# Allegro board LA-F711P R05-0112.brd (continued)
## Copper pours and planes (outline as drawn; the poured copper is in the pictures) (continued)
+PWR_SRC on TOP (solid shape): 130.69,128.12 131.24,128.12 131.24,128.66 131.49,128.66 131.49,128.12 132.95,128.12 133.78,127.28 133.78,124.36 135.17,122.96 135.17,117.62 133.97,116.42 130.15,116.42 129.77,116.04 129.77,115.28 131.11,113.94 136.32,113.94 136.7,113.56 136.7,112.42 136.44,112.17 135.47,112.17 135.45,112.14 129.38,112.14 128,110.77 127.17,110.77 127.04,110.9 127.04,111.28 127.11,111.34 127.89,111.34 128.49,111.94 128.49,113.97 127.43,115.03 125.3,115.03 124.84,115.48 124.84,116.73 125.75,117.63 125.75,122.21 128.93,125.39 128.93,127.92 129.13,128.12 130.44,128.12 130.44,128.66 130.69,128.66
+PWR_SRC on BOTTOM (solid shape): 136.44,114.07 136.44,112.55 136.19,112.29 133.9,112.29 133.52,112.67 133.52,114.07 133.78,114.32 136.19,114.32
+PWR_SRC on BOTTOM (solid shape): 37.73,59.94 40.8,59.94 41.85,58.9 41.85,54.43 40.92,53.49 35.61,53.49 35.39,53.71 35.39,54.99 35.63,55.22 36.17,55.22 36.29,55.35 36.29,59.41 36.3,59.41 36.3,60.32 36.41,60.43 37.25,60.43
+PWR_SRC on BOTTOM (solid shape): 79.65,6.22 80.69,6.22 80.77,6.14 80.77,5.65 81.32,5.65 81.32,5.39 80.77,5.39 80.77,4.85 81.32,4.85 81.32,4.59 80.77,4.59 80.77,3.69 80.32,3.24 78.22,3.24 78.08,3.38 78.08,6.46 78.24,6.63 79.24,6.63
+PWR_SRC on BOTTOM (solid shape): outline of 270 points within 20.47,1.42 168.28,41.53
+PWR_SRC on TOP: outline of 116 points within 19.44,1.37 80.6,58.44
+PWR_SRC on TOP: 161.15,6.64 162.44,6.64 163,6.08 163.35,6.08 163.35,6.08 163.71,6.08 164.38,5.4 164.38,3.14 164.3,3.05 163.6,3.05 163.23,3.42 163.23,4.19 161.67,5.75 161.1,5.75 160.98,5.87 160.98,6.48
+PWR_SRC on BOTTOM: 160.99,6.55 162.16,6.55 162.77,5.94 164.13,5.94 164.25,5.83 164.25,3.73 164.08,3.57 163.01,3.57 160.9,5.68 160.9,6.46
+PWR_SRC on IN1: 156.88,3.19 155.94,4.13 155.94,6.74 156.35,7.15 162.05,7.15 162.44,6.76 162.44,6.18 163.06,5.56 163.06,5.03 162.94,4.9 161.73,4.9 161.43,5.21 160.68,5.21 160.45,5.22 160.22,5.21 159.41,5.21 157.39,3.19
+PWR_SRC on IN1: 81.64,1.31 81.58,1.37 40.38,1.37 40.38,1.37 34.91,1.37 32.78,3.5 29.84,3.5 20.65,12.7 20.65,16.26 20.24,16.66 20.24,20.52 21.43,21.72 21.42,21.72 21.42,22.73 22.13,23.44 22.13,26.3 24.93,29.1 24.93,39.85 23.54,41.24 23.54,51.23 30.88,58.57 39.86,58.57 40.09,58.34 40.09,54.11 39.85,53.87 34.46,53.87 30.02,49.43 30.02,45.73 29.99,45.65 29.91,45.62 28.97,44.74 29.91,43.85 29.99,43.82 30.02,43.75 30.02,42.21 29.75,42.48 29.43,42.48 29.21,42.26 29.21,39.9 30.02,39.08 30.02,37.24 31.29,35.97 31.29,27.58 26.44,22.73 26.44,18.93 26.14,18.2 26.44,17.46 26.44,16.33 26.44,16.28 26.44,16.24 26.44,14.99 26.45,14.97 26.45,14.13 29.43,11.15 35.07,11.15 36.18,10.05 36.18,6.21 36.72,5.66 41.3,5.66 41.41,5.55 41.47,5.55 41.88,5.13 41.88,5.1 42.59,4.4 42.59,3.43 42.97,3.05 77.26,3.05 78.47,4.26 78.47,5.73 78.99,6.26 80.35,6.26 80.36,6.24 80.79,6.24 80.93,6.1 80.93,3.7 82.31,2.33 86.33,2.33 86.46,2.2 86.46,1.31
+PWR_SRC on VCC: 18.72,1.17 18.72,35.16 22.91,39.35 22.91,57.37 36.92,57.37 37.36,57.81 39.99,57.81 39.99,45.15 23.61,28.77 23.61,13.32 26.23,10.69 35.44,10.69 36.05,10.08 36.05,6.59 38.3,4.34 42.61,4.34 43.63,3.33 76.1,3.33 78.89,6.12 80.33,6.12 81.2,5.25 81.2,1.17
+PWR_SRC_AC on TOP (solid shape): 22.53,53.52 22.53,45.11 22.14,44.73 17.57,44.73 17.19,45.11 17.19,47.6 13.52,51.27 13.52,54.3 13.42,54.41 12.76,54.41 12.56,54.61 12.56,55.13 12.58,55.16 13.33,55.16 13.48,55.3 13.48,55.75 13.31,55.92 12.63,55.92 12.56,55.99 12.56,57.03 12.78,57.25 18.79,57.25
+PWR_SRC_AC on BOTTOM (solid shape): 22.53,47.95 22.53,47.34 22.53,47.33 22.53,45.31 22.05,44.83 20.45,44.83 20.45,44.32 19.96,44.32 19.96,44.83 19.25,44.83 19.25,44.32 18.76,44.32 18.76,44.83 17.98,44.83 17.1,45.72 17.1,47.38 18.2,48.49 21.99,48.49
+REGCTL_PNP10 on TOP (solid shape): 327.19,87.15 327.19,85.88 327.06,85.76 325.99,85.76 325.54,86.2 325.03,86.2 324.84,86.39 323.82,86.39 323.76,86.45 323.76,86.58 323.81,86.63 325.78,86.63 326.43,87.28 327.06,87.28
+RREF on TOP (solid shape): 16.55,66.26 16.55,65.5 16.17,65.12 14.83,65.12 14.07,64.36 14.07,63.47 14.01,63.4 13.5,63.4 13.44,63.47 13.44,64.42 14.71,65.69 15.72,65.69 16.36,66.32 16.49,66.32
+RSVD_VCC3P3_1 on TOP (solid shape): 325.09,83.85 325.09,83.22 324.9,83.03 324.65,83.03 323.76,83.91 323.76,84.17 323.82,84.23 324.71,84.23
+RTC_CELL_PCH on TOP: 213.2,16.75 213.2,15.8 213.8,15.2 213.8,12.22 214.16,11.86 216.02,11.86 216.42,12.25 216.42,14.46 217.18,15.23 217.18,16.73 217.09,16.81 213.27,16.81
+SDC_IN on TOP (solid shape): 11.55,60.86 11.55,56.02 11.46,55.93 10.83,55.93 10.62,55.72 10.62,55.29 10.75,55.17 11.5,55.17 11.54,55.13 11.54,54.63 11.31,54.41 3.27,54.41 2.36,55.32 2.36,64.45 2.98,65.07 7.34,65.07
+SDC_IN on TOP (solid shape): outline of 140 points within 39.63,87.88 61.13,119.53
+SDC_IN on IN1 (solid shape): 8.58,68.4 8.58,59.64 7.39,58.44 3.6,58.44 3.48,58.57 3.48,68.26 3.74,68.53 8.45,68.53
+SDC_IN on IN1 (solid shape): 43.89,97.19 43.89,91.27 43.9,91.27 44.03,91.15 44.03,88.91 43.73,88.62 41.41,88.62 40.79,89.24 40.79,97.05 41.17,97.43 43.65,97.43
+TBTA_VBUS on TOP (solid shape): 7.78,112.48 10.4,112.48 10.71,112.17 11.1,112.17 11.35,111.91 11.35,111.28 11.12,111.05 8.51,111.05 7.97,111.58 6.9,111.58 6.7,111.78 6.7,112.39 6.78,112.47 7.21,112.47 7.39,112.65 7.61,112.65
+TBTA_VBUS on TOP (solid shape): outline of 201 points within 6.72,114.61 13.89,124.23
+TBTA_VBUS on BOTTOM (solid shape): 17.83,124.99 17.83,119.73 17.78,119.68 11.3,119.68 10.15,120.83 10.15,121.26 10.42,122.24 10.44,123.25 10.41,123.43 10.38,123.6 10.4,123.69 10.48,123.72 10.91,124.16 11.3,124.16 11.32,124.13 12.84,124.13 13.38,123.6 14.14,123.6 14.65,124.1 14.65,124.87 15.03,125.25 17.57,125.25
+TBTA_VBUS on BOTTOM (solid shape): 10.68,112.19 11.13,112.19 11.22,112.1 11.22,111.72 10.91,111.4 9.87,111.4 9.17,112.11 8.97,112.11 8.71,112.36 8.13,112.36 8.07,112.39 8,112.39 7.39,112.39 7.21,112.32 7.13,112.14 6.95,111.96 6.85,111.96 6.59,112.23 6.03,112.23 5.97,112.29 5.97,112.47 6,112.51 6.7,112.51 6.97,112.45 7.2,112.6 7.45,112.85 10.02,112.85
+TBTA_VBUS on BOTTOM (solid shape): 10.66,115.52 10.66,114.7 10.44,114.47 9.04,114.47 8.65,114.86 8.13,114.86 8.07,114.89 8,114.89 7.39,114.89 7.31,114.88 7.23,114.84 7.15,114.87 6.89,114.91 6.73,114.85 6.59,114.85 6.5,114.76 5.86,114.76 5.86,114.99 6.32,114.99 6.46,115.13 6.5,115.13 6.66,115.19 6.74,115.34 6.75,115.35 6.93,115.35 6.94,115.37 7.5,115.37 7.52,115.38 7.55,115.38 8.15,115.38 8.17,115.37 8.72,115.37 9.04,115.68 9.15,115.68 9.17,115.7 10.49,115.7
+TBTA_VBUS on IN1 (solid shape): outline of 350 points within 6.72,111.48 13.89,124.23
+TBTA_VBUS on IN2 (solid shape): outline of 281 points within 6.6,111.4 14.17,124.51
+TBTA_VBUS_1 on TOP (solid shape): 24.06,124.9 24.06,123.6 24.61,123.6 24.61,123.15 24.06,123.15 24.06,122.4 24.61,122.4 24.61,121.95 24.06,121.95 24.06,120.56 23.92,120.42 19.22,120.42 18.59,121.06 18.59,124.48 19.1,124.99 23.97,124.99
+TBTA_VBUS_1 on TOP (solid shape): outline of 407 points within 30.62,85.01 39.7,114.07
+TBTA_VBUS_1 on BOTTOM (solid shape): 24.43,124.43 24.43,120.55 24.25,120.37 19.94,120.37 19.5,120.8 18.87,120.8 18.59,121.08 18.59,124 18.77,124.18 21.79,124.18 22.22,124.61 24.25,124.61
+TBTA_VBUS_1 on BOTTOM (solid shape): 34.06,112.93 34.06,112.08 33.74,111.76 32.66,111.76 32.09,111.19 32.09,110.86 32.08,110.85 32.08,109.75 31.9,109.58 31.06,109.58 30.65,109.98 30.65,113.64 31.09,114.07 32.91,114.07
+TBTA_VBUS_1 on BOTTOM (solid shape): 38.68,92.23 38.68,91.34 38.55,91.21 37.51,91.21 37.48,91.18 37.37,91.18 37.37,91.08 37.11,90.82 37.11,90.07 36.12,89.08 35.57,89.08 35.55,89.1 35.28,89.1 35.26,89.1 35.24,89.11 35.17,89.18 35.17,89.38 35.05,89.5 34.83,89.5 34.71,89.63 34.71,89.89 34.73,89.96 34.79,89.99 34.95,89.99 35.08,90.09 35.1,90.09 35.25,90.25 35.25,90.3 35.43,90.48 35.45,90.48 35.54,90.54 35.59,90.63 35.59,90.64 35.68,90.72 35.68,90.92 36.45,91.69 36.86,91.69 37.13,91.97 37.13,92.03 37.5,92.4 38.5,92.4
+TBTA_VBUS_1 on IN1 (solid shape): 27.5,122.07 27.97,122.07 28.01,122.07 28.7,122.07 28.74,122.07 29.24,122.07 29.27,122.06 29.32,122.04 29.38,122.02 29.43,122.02 29.49,122.02 29.55,122.04 29.6,122.06 29.63,122.07 32.31,122.07 34.08,120.3 34.08,117.73 36.14,115.67 36.14,112.39 35.74,111.99 33.02,111.99 32.03,112.99 32.03,115.82 31.47,116.38 31.47,116.43 29.79,118.11 24.35,118.11 22.53,119.94 20.8,119.94 20.11,120.63 27.15,120.63 27.15,120.57 27.16,120.52 27.17,120.47 27.2,120.42 27.23,120.38 27.26,120.34 27.3,120.3 27.35,120.28 27.4,120.26 27.45,120.25 27.5,120.24 27.56,120.25 27.61,120.26 27.66,120.28 27.71,120.3 27.75,120.34 27.78,120.38 27.81,120.42 27.84,120.47 27.85,120.52 27.86,120.57 27.86,120.63 27.85,120.68 27.84,120.73 27.81,120.78 27.78,120.82 27.75,120.86 27.71,120.89 27.66,120.92 27.61,120.94 27.56,120.95 27.5,120.96 27.45,120.95 27.4,120.94 27.35,120.92 27.3,120.89 27.26,120.86 27.23,120.82 27.2,120.78 27.17,120.73 27.16,120.68 27.15,120.63 20.11,120.63 19.48,121.26 19.48,123.32 20.26,124.1 25.47,124.1
+USB_EX2_PWR on BOTTOM (solid shape): 20.9,96.34 20.9,95.45 20.57,95.12 19.1,95.12 18.82,94.84 18.82,93.24 18.77,93.19 18.77,92.43 18.61,92.28 15.87,92.28 15.82,92.33 15.81,92.35 15.6,92.76 15.19,92.97 15.17,92.98 14.45,93.7 14.45,95.76 15.31,96.62 20.62,96.62
+USB_EX3_PWR on TOP (solid shape): 91.26,126.19 91.26,124 91.4,123.86 93.43,123.86 93.72,123.57 93.72,122.55 93.29,122.12 90.5,122.12 90.27,122.35 89.84,122.35 88.74,123.44 88.74,126.42 89.15,126.82 90.62,126.82
+USB_EX3_PWR on BOTTOM (solid shape): 93.54,125.83 93.54,123.29 94.36,122.48 96.31,122.48 96.62,122.17 96.62,121.44 96.57,121.39 96.57,120.24 96.11,119.79 92.73,119.79 92.3,120.22 92.3,120.8 95.19,120.8 95.2,120.75 95.21,120.69 95.23,120.64 95.26,120.59 95.29,120.55 95.33,120.51 95.38,120.48 95.43,120.45 95.48,120.43 95.53,120.42 95.59,120.42 95.65,120.43 95.7,120.44 95.75,120.46 95.8,120.49 95.84,120.53 95.88,120.57 95.91,120.61 95.93,120.67 95.95,120.72 95.96,120.77 95.96,120.83 95.95,120.89 95.93,120.94 95.91,120.99 95.88,121.04 95.84,121.08 95.8,121.11 95.75,121.14 95.7,121.16 95.65,121.18 95.59,121.18 95.53,121.18 95.48,121.17 95.43,121.15 95.38,121.13 95.33,121.1 95.29,121.06 95.26,121.01 95.23,120.96 95.21,120.91 95.2,120.86 95.19,120.8 92.3,120.8 91.03,122.07 91.03,123.16 90.83,123.37 89.96,123.37 89.01,124.32 89.01,126.38 89.48,126.85 92.53,126.85
+UZ12_VHIO on TOP: 242.14,27.62 242.14,29.13 242.29,29.28 242.29,30.28 242.07,30.5 242.07,31.46 242.17,31.55 243.54,31.55 243.73,31.36 243.73,29.86 243.96,29.63 245.01,29.63 245.08,29.56 245.08,29.43 245.03,29.37 244.17,29.37 243.8,29 243.8,27.69 243.68,27.58 242.19,27.58
+VCHGR on TOP (solid shape): 25.19,5.38 25.19,4.93 25.05,4.79 24.43,4.79 24.26,4.62 24.26,4.25 24.49,4.03 25.17,4.03 25.19,4.01 25.19,3.45 25.04,3.3 24.43,3.3 23.97,2.84 23.97,1.49 23.77,1.28 21.04,1.28 20.93,1.4 20.93,5.59 21.08,5.74 24.84,5.74
+VHDMI_VCC on BOTTOM: 115.19,124.51 115.57,124.13 117.09,124.13 117.8,124.84 117.8,125.63 118.54,126.36 120.81,126.36 122.27,124.9 122.27,124.64 122.21,124.57 122.21,124.09 121.87,123.75 121.05,123.75 118.77,121.46 113.46,121.46 112.77,122.15 112.77,128.17 112.57,128.37 112.57,128.56 112.57,128.57 112.63,128.8 112.59,129.03 112.58,129.06 112.82,129.31 114.24,129.31 114.32,129.28 114.35,129.21 114.51,128.91 114.94,128.87 114.98,128.79 114.98,127.86 115.19,127.66 115.19,125.88 115.15,125.81 115.08,125.78 114.69,125.42 115.08,125.07 115.15,125.04 115.19,124.97
+VR_CAP on TOP (solid shape): 313.97,34.07 313.97,33.75 313.91,33.69 313.55,33.69 313.5,33.64 313.39,33.64 312.82,33.07 311.04,33.07 310.82,32.85 310.31,32.85 310.17,32.99 310.17,33.79 310.43,34.06 310.46,34.07 310.49,34.09 310.69,34.09 310.9,33.87 312.5,33.87 312.8,34.17 313.15,34.17 313.16,34.17 313.86,34.17
ADP_ISL88738 on TOP (solid shape): 13.42,36.35 13.42,36.08 13.23,35.89 12.96,35.89 12.71,35.64 12.71,35.38 12.42,35.09 11.53,35.09 11.51,35.11 11.51,35.28 11.55,35.32 12.18,35.32 12.3,35.45 12.3,35.97 12.81,36.47 13.29,36.47
BGATE_ISL88738 on TOP (solid shape): 22.7,6.78 23.41,6.78 23.44,6.76 23.44,6.12 23.24,5.92 21.1,5.92 21.03,5.99 21.03,6.55 21.28,6.81 22.68,6.81
BGATE_ISL88738 on TOP (solid shape): 8.07,32.41 8.07,32.3 8.03,32.26 7.39,32.26 6.61,31.48 6.44,31.48 6.3,31.62 6.3,31.85 6.46,32.01 6.71,32.01 7.17,32.47 8.02,32.47
BOOT1_ISL88738 on BOTTOM (solid shape): 14.29,34.2 14.29,33.38 14.23,33.32 13.61,33.32 13.34,33.59 12.96,33.59 12.8,33.76 12.8,33.76 12.8,34.01 13.03,34.24 14.25,34.24
BOOT2_ISL88738 on TOP: 9.56,32.14 9.66,32.14 9.71,32.09 9.71,31.13 9.43,30.85 9.43,29.95 9.62,29.76 9.88,29.76 9.9,29.73 9.9,29.13 9.81,29.04 9.03,29.04 8.92,29.15 8.92,29.88 9.09,30.05 9.09,30.78 9.51,31.2 9.51,32.09
BST_3V on BOTTOM (solid shape): 89.15,5.89 89.15,4.6 88.93,4.38 88.93,3.49 88.85,3.4 88.24,3.4 88.18,3.45 88.18,4.52 88.74,5.08 88.74,5.99 88.82,6.07 88.97,6.07
BST_5V on TOP (solid shape): 127.15,131.34 127.15,130.4 127.12,130.38 126.26,130.38 125.47,131.17 125.01,131.17 124.91,131.27 124.91,131.42 124.96,131.47 127.02,131.47
BST_+1VALWP on BOTTOM (solid shape): 169.25,5.27 169.25,4.46 169.85,3.86 169.85,3.21 169.82,3.19 168.97,3.19 168.93,3.23 168.93,3.94 169,4 169,5.3 169.05,5.35 169.17,5.35
BST_+1VALWP_R on BOTTOM (solid shape): 171.05,2.46 171.05,1.78 168.96,1.78 168.93,1.8 168.93,2.45 168.98,2.5 171.01,2.5
CNV_RF_RST on BOTTOM (solid shape): 296.31,44.64 296.31,43.85 296.09,43.64 294.86,43.64 294.62,43.88 294.62,44.43 294.76,44.57 295.45,44.57 295.65,44.77 296.18,44.77
CORE_SW1 on BOTTOM (solid shape): 67.89,97.45 67.89,96.16 68.02,96.02 72.53,96.02 73.31,95.24 75.05,95.24 75.57,94.73 77.78,94.73 77.82,94.68 77.82,92.24 77.81,92.23 77.81,92.11 77.76,92.06 76.45,92.06 76.41,92.09 76.41,92.97 76.39,92.98 75.6,92.98 75.59,92.98 75.59,92.07 75.58,92.06 73.8,92.06 73.67,92.19 73.67,92.19 73.56,92.3 73.55,92.3 72.79,93.07 71,93.07 70.71,93.35 70.71,94.12 70.46,94.37 67.52,94.37 67.51,94.38 67.35,94.38 67.12,94.6 67.12,97.46 67.17,97.51 67.83,97.51
CORE_SW1 on TOP: 75.49,92.03 74.53,92.03 74.47,92.09 74.47,92.68 74.25,92.9 73.62,92.9 73.48,93.05 73.48,93.75 73.6,93.87 74.74,93.87 75.59,93.02 75.59,92.13
CORE_SW2 on BOTTOM (solid shape): 77.33,97.62 77.33,96.77 77.45,96.65 77.45,96.31 77.6,96.16 81.43,96.16 81.96,95.63 82.28,95.63 82.28,95.63 83.25,95.63 83.65,95.23 84.99,95.23 85.26,94.95 85.26,93.32 85.26,93.32 85.26,92.11 85.22,92.07 84.01,92.07 83.93,92.16 83.93,92.97 83.91,92.99 83.12,92.99 83.1,92.98 83.1,92.08 83.09,92.07 78.76,92.07 78.13,92.7 78.13,94.71 76.92,95.91 76.92,96.22 76.63,96.51 76.63,97.64 76.64,97.65 77.3,97.65
CORE_SW3 on BOTTOM: 91.35,100.49 90.7,100.49 90.61,100.4 90.61,96.67 90.46,96.52 89.25,96.52 89.12,96.39 89.12,92.42 89.28,92.26 90.62,92.26 90.65,92.28 90.65,93.21 90.66,93.21 91.45,93.21 91.46,93.21 91.46,92.3 91.48,92.28 95.65,92.28 95.88,92.52 95.88,95.39 95.37,95.9 93.68,95.9 93.25,96.34 93.25,97.3 91.58,98.96 91.58,98.96 91.5,99.05 91.5,100.34
CORE_SW4 on BOTTOM (solid shape): 103.26,99.93 103.26,96.38 102.75,95.86 102.75,94.06 102.18,93.49 102.19,93.49 102.19,92.47 102.02,92.3 99,92.3 98.97,92.32 98.97,93.23 98.97,93.23 98.18,93.23 98.17,93.23 98.17,92.3 98.14,92.28 96.53,92.28 96.19,92.62 96.19,93.24 96.77,93.83 96.77,94.67 96.85,94.74 98.64,94.74 98.76,94.86 98.76,96.45 98.8,96.49 99.92,96.49 100.05,96.62 100.05,100.29 100.14,100.39 102.8,100.39
CPU_B+ on BOTTOM (solid shape): 65.4,96.27 65.4,91.85 64.72,91.16 61.98,91.16 61.76,91.39 61.76,94.63 63.64,96.51 65.15,96.51
CPU_B+ on IN3 (solid shape): 88.02,101.78 88.02,99.7 87.72,99.39 86.5,99.39 86.35,99.55 86.35,100.3 85.63,101.01 85.63,101.84 85.87,102.09 87.71,102.09
CPU_B+ on IN3 (solid shape): 97.12,102.89 97.13,102.89 97.53,102.49 97.53,99.69 97.49,99.64 95.9,99.64 94.46,101.08 94.46,102.84 94.66,103.05 96.97,103.05
CPU_B+ on IN3 (solid shape): 73.78,101.02 73.78,98.96 73.44,98.62 73.19,98.62 72.66,98.62 72.66,98.62 71.12,98.62 70.84,98.89 70.84,100.96 71.17,101.29 71.17,101.3 73.51,101.3
CPU_B+ on IN3 (solid shape): 83.06,101.58 83.06,98.94 82.84,98.72 80.81,98.72 80.54,98.99 80.54,100.04 81.09,100.59 81.09,101.54 81.28,101.72 81.28,101.72 81.4,101.83 82.81,101.83
CPU_B+ on TOP: 82.24,98.84 80.76,98.84 80.53,99.07 80.53,100.47 81.16,101.09 81.16,102.78 81.26,102.88 87.53,102.88 87.72,103.07 87.72,104.3 87.87,104.45 88.36,104.45 88.58,104.23 88.58,101.29 88.02,100.72 87.99,100.72 87.99,99.63 87.8,99.43 86.67,99.43 86.54,99.56 86.54,99.77 86.53,99.77 86.53,100.51 86.34,100.7 84.16,100.7 83.68,100.23 83.68,99.85 83.68,99.85 83.68,99.41 83.56,99.29 83.56,99.28 82.67,99.28
CPU_B+ on TOP: 72.31,101.94 72.83,101.94 73.4,102.51 73.4,103.5 73.57,103.68 74.35,103.68 74.6,103.42 74.6,99.71 74.24,99.35 74.24,98.54 74.09,98.39 72.97,98.39 72.72,98.64 71.21,98.64 71.04,98.81 71.04,100.12 72.22,101.29 72.22,101.84
CPU_B+ on TOP: 95.89,104 96.62,104 96.97,103.66 96.97,101.77 97.5,101.24 97.5,99.33 97.36,99.19 96.37,99.19 96.23,99.33 96.23,100.71 96.09,100.85 94.02,100.85 93.9,100.98 93.9,104.83 93.97,104.9 95,104.9
CPU_B+ on BOTTOM: 35.09,60.83 35.25,60.67 40.85,60.67 40.94,60.76 40.94,64.05 39.96,65.02 39.96,65.77 39.38,66.36 35.42,66.36 35.09,66.03
CPU_B+ on BOTTOM: 86.84,98.49 86.77,98.56 86.77,99.88 86.63,100.02 85.83,100.02 85.65,100.2 85.65,104.49 85.87,104.71 85.87,105.65 85.87,105.69 85.6,105.96 83.15,105.96 82.72,105.54 82.72,104.5 82.73,104.5 82.73,103.44 82.72,103.43 82.72,101.55 82.77,101.5 83.58,101.5 83.63,101.45 83.63,99.55 83.49,99.42 82.67,99.42 82.13,98.88 79.52,98.88 79.47,98.93 79.47,99.18 79.47,99.19 79.47,100 79.56,100.08 80.87,100.08 81,100.21 81,100.41 81,101.72 80.92,101.79 80.75,101.79 80.65,101.89 80.65,102.58 80.4,102.83 80.4,107.06 80.63,107.29 93.03,107.29 95.54,104.77 96.62,104.77 96.93,104.46 96.93,101.77 97.21,101.49 97.4,101.49 97.54,101.36 97.54,98.66 97.48,98.59 96.41,98.59 96.35,98.65 96.35,99.74 95.97,100.13 95.43,100.13 95.34,100.22 95.34,100.35 94.89,100.8 94.89,101.93 94.77,102.05 91.84,102.05 91.7,102.18 91.7,103.98 91.59,104.09 89.02,104.09 88.61,103.68 88.61,101.41 88.24,101.05 88.24,101.04 87.95,100.75 87.95,98.55 87.89,98.49
CPU_B+ on BOTTOM: 72.77,98.67 70.05,98.67 70.03,98.69 70.03,99.82 70.05,99.84 71.31,99.84 71.55,100.08 71.55,100.8 71.67,100.93 72.02,100.93 72.26,101.17 72.26,101.99 72.32,102.05 75.63,102.05 76.02,101.66 76.02,100.24 75.22,99.44 74.44,99.44 74.13,99.12 74.13,98.21 74.04,98.12 73.32,98.12
CPU_B+ on BOTTOM: 105.97,100.14 105.22,100.14 105.22,99.6 105.22,99.6 104.77,99.6 104.77,99.6 104.77,100.14 104.77,100.14 104.02,100.14 104.02,99.6 104.02,99.6 103.49,99.6 103.42,99.66 103.42,100.84 103.76,101.18 103.77,101.18 103.91,101.33 106.69,101.33 106.82,101.2 106.82,99.92 106.5,99.6 105.97,99.6 105.97,99.6 105.97,100.14
CPU_B+ on IN1: 54.63,100.4 62.99,100.4 63.43,100.85 63.43,100.86 65.6,103.03 74.1,103.03 75.48,104.42 93.15,104.42 93.99,103.58 98.93,103.58 100.78,101.73 100.78,101.71 101.47,101.03 106.73,101.03 106.99,100.76 106.99,97.68 104.72,95.4 73.28,95.4 72.69,94.81 61.59,94.81 60.42,93.64 58.16,93.64 56.65,92.13 54.59,92.13 53.84,91.37 53.84,89.94 52.83,88.93 50.84,88.93 50.04,88.13 50.04,85.78 50.53,85.29 50.53,84.95 49.6,84.02 49.6,77.79 43.37,71.55 43.37,66.81 42.27,65.72 42.27,63.09 41.73,62.55 34.15,62.55 32.72,63.98 32.72,69.29 35.65,72.21 35.65,73.08 35.62,73.1 35.62,75.3 40.66,80.34 40.66,86.17 41.89,87.4 43.61,87.4 44.64,88.43 44.64,90.41 44.66,90.44 44.66,93.91 48.69,97.94 52.16,97.94
CPU_B+ on VCC: 35.61,62.64 35.61,73.3 38,73.3 40.12,75.42 40.12,77.96 42.34,80.18 42.34,88.12 54.76,100.55 62.76,100.55 65.3,103.09 72.29,103.09 73.62,104.42 104.21,104.42 106.98,101.65 106.98,97.6 104.78,95.4 73.28,95.4 72.71,94.83 61.66,94.83 58.93,92.1 54.62,92.1 53.22,90.7 52.58,90.7 49.89,88.01 49.89,86.53 50.15,86.28 50.15,84.9 49.58,84.33 49.58,77.73 43.35,71.5 43.35,66.81 42.27,65.73 42.27,62.64
DCIN_ISL88738 on TOP: 11.2,35.38 11.44,35.38 11.95,35.89 11.95,36.47 13.55,38.07 13.55,38.82 13.47,38.9 12.75,38.9 12.18,38.33 12.18,37.45 11.12,36.4 11.12,35.46
EN_+1VALWP on TOP: 165.45,9.66 167.8,9.66 167.97,9.5 167.97,8.33 167.56,7.92 166.56,7.92 166.12,8.36 166.12,8.69 165.82,8.99 165.6,8.99 165.39,9.21 165.39,9.6
GT_SW1 on BOTTOM: 52.12,66.7 48.36,66.7 48.03,66.37 48.03,62.59 47.85,62.41 46.55,62.41 46.5,62.36 46.5,61.42 47.72,60.2 48.69,60.2 48.94,60.45 48.94,61.01 50.26,62.33 52.19,62.33 52.24,62.38 52.24,63.7 52.19,63.75 51.35,63.75 51.3,63.8 51.3,64.52 51.33,64.54 52.19,64.54 52.22,64.57 52.22,66.6
HDD_UN7_EN on TOP: 269.49,11.81 268.33,11.81 268.09,11.57 268.09,10.06 268.37,9.78 269.3,9.78 269.66,10.13 270.68,10.13 270.79,10.24 270.79,10.77 270.6,10.96 269.86,10.96 269.67,11.15 269.67,11.63
INT_SPK_L+ on TOP (solid shape): 349.02,25.05 349.02,24.22 348.89,24.09 347.88,24.09 347.81,24.16 347.81,25.11 347.88,25.17 348.89,25.17
INT_SPK_L+ on TOP (solid shape): 338.73,38.02 338.73,37.9 338.68,37.85 337.17,37.85 336.94,37.63 335.92,37.63 335.92,37.63 335.85,37.63 335.61,37.39 334.78,37.39 334.72,37.45 334.72,38.02 334.78,38.08 338.66,38.08
INT_SPK_L+ on IN2 (solid shape): 348.96,25.05 348.96,24.22 348.83,24.09 348.26,24.09 347.18,25.17 347.18,25.3 347.69,25.81 348.19,25.81
INT_SPK_L+ on IN2 (solid shape): 338.98,37.7 338.98,35.88 338.82,35.72 338.09,35.72 337.95,35.86 337.95,37.33 337.7,37.58 336.3,37.58 336.22,37.59 336.13,37.58 335.36,37.58 335.28,37.67 335.28,38.15 335.34,38.22 338.47,38.22
INT_SPK_L- on TOP (solid shape): 349.41,22.88 349.41,22.14 349.21,21.93 347.88,21.93 347.81,22 347.81,22.95 347.88,23.01 349.28,23.01
INT_SPK_L- on TOP (solid shape): 338.72,37.61 338.72,37.52 338.67,37.47 338.59,37.47 338.59,37.47 337.28,37.47 336.78,36.98 336.37,36.98 335.89,36.5 334.78,36.5 334.72,36.57 334.72,37.14 334.85,37.26 335.74,37.26 335.98,37.5 337.02,37.5 337.19,37.67 338.66,37.67
INT_SPK_L- on IN2 (solid shape): 349.02,22.82 349.02,22.13 348.83,21.93 347.75,21.93 347.43,22.25 347.43,22.7 347.75,23.01 348.83,23.01
INT_SPK_L- on IN2 (solid shape): 337.68,37.03 337.68,35.31 337.63,35.26 336.78,35.26 336.68,35.36 336.68,36.63 336.56,36.76 335.55,36.76 335.42,36.88 335.42,37.26 335.55,37.39 337.32,37.39
INT_SPK_R+ on TOP (solid shape): 349.02,21.11 349.02,20.28 348.89,20.16 347.88,20.16 347.81,20.22 347.81,21.17 347.88,21.24 348.89,21.24
INT_SPK_R+ on TOP (solid shape): 338.72,36.83 338.72,36.73 338.65,36.66 337.66,36.66 336.97,35.97 336.97,35.45 336.31,34.79 334.78,34.79 334.72,34.85 334.72,35.36 334.85,35.49 336.15,35.49 337.55,36.88 338.67,36.88
INT_SPK_R+ on IN2 (solid shape): 349.08,21.05 349.08,20.35 348.89,20.16 347.62,20.16 347.31,20.47 347.31,21.11 347.43,21.24 348.89,21.24
INT_SPK_R+ on IN2 (solid shape): 336.39,35.25 336.39,33.79 335.77,33.17 335.2,33.17 334.91,33.46 334.91,33.74 335.39,34.21 335.39,34.78 335.32,34.85 335.32,35.32 335.42,35.42 336.21,35.42
INT_SPK_R- on TOP (solid shape): 349.24,19.68 349.24,18.47 349.08,18.31 347.85,18.31 347.81,18.35 347.81,19.57 348,19.75 349.16,19.75
INT_SPK_R- on TOP (solid shape): 338.73,37.22 338.73,37.12 338.67,37.07 337.52,37.07 336.13,35.68 334.78,35.68 334.72,35.74 334.72,36.25 334.78,36.31 335.93,36.31 336.34,36.73 336.74,36.73 337.29,37.28 338.67,37.28
INT_SPK_R- on IN2 (solid shape): 349.3,19.62 349.3,18.66 349.08,18.43 347.46,18.43 347.12,18.78 347.12,19.22 347.65,19.75 349.18,19.75
INT_SPK_R- on IN2 (solid shape): 336.5,36.31 336.5,36.06 336.21,35.77 335.32,35.77 334.94,35.39 334.94,34.5 334.75,34.31 334.12,34.31 333.93,34.5 333.93,35.77 334.66,36.5 336.31,36.5
INT_SPKR_L+ on TOP (solid shape): 347.56,25.17 347.56,24.28 347.5,24.22 346.48,24.22 346.23,24.47 344,24.47 343.69,24.16 342.67,24.16 341.84,23.33 341.01,23.33 340.76,23.58 340.76,23.83 342.1,25.17 343.24,25.17 343.69,25.62 347.11,25.62
INT_SPKR_L+ on BOTTOM (solid shape): 341.97,24.28 341.97,23.46 341.84,23.33 341.02,23.33 340.76,23.59 339.11,23.59 338.86,23.84 338.86,24.16 339.11,24.41 341.84,24.41
INT_SPKR_L- on TOP (solid shape): 344.07,22.95 347.56,22.95 347.62,22.89 347.62,22.06 347.56,22 342.8,22 342.67,22.13 340.96,22.13 340.83,22.25 340.83,22.82 341.02,23.01 342.16,23.01 342.35,23.2 343.81,23.2
INT_SPKR_L- on BOTTOM (solid shape): 341.97,22.95 341.97,22.44 341.84,22.32 339.05,22.32 338.86,22.51 338.86,22.95 339.05,23.14 341.78,23.14
INT_SPKR_R+ on TOP (solid shape): 342.73,21.24 344.07,21.24 344.19,21.36 347.37,21.36 347.56,21.17 347.56,20.35 347.5,20.28 346.61,20.28 346.42,20.47 344.51,20.47 344.19,20.16 342.73,20.16 341.97,20.92 341.15,20.92 340.89,21.17 340.89,21.43 341.08,21.62 342.35,21.62
INT_SPKR_R+ on BOTTOM (solid shape): 341.97,21.68 341.97,21.24 341.84,21.11 338.99,21.11 338.86,21.24 338.86,21.68 339.05,21.87 341.78,21.87
INT_SPKR_R- on TOP (solid shape): 343.04,19.27 343.75,19.27 344.19,18.82 346.48,18.82 346.8,19.14 347.56,19.14 347.62,19.08 347.62,18.32 347.18,17.87 342.99,17.87 342.25,18.61 342.16,18.76 342.02,18.84 340.89,19.97 340.89,20.22 340.9,20.22 340.9,20.46 341.05,20.62 341.69,20.62
INT_SPKR_R- on BOTTOM (solid shape): 342.22,20.37 342.22,20.05 342.01,19.84 339.11,19.84 338.86,20.09 338.86,20.47 339.05,20.66 341.92,20.66
LDO_3V on BOTTOM: 170.93,8.09 171.62,8.09 171.65,8.06 171.65,7.21 171.55,7.11 170.75,7.11 170.4,6.77 169.4,6.77 169.33,6.84 169.33,7.42 169.39,7.48 170.32,7.48
LG1_ISL88738 on TOP (solid shape): 20.35,30.37 20.35,29.49 20.11,29.25 19.05,29.25 18.92,29.37 18.92,30.25 19.16,30.49 20.23,30.49
LG1_ISL88738 on TOP (solid shape): 11.52,32.52 12.21,32.52 12.37,32.36 12.37,32.03 12.8,31.6 12.8,31.22 13.28,30.73 13.28,30.31 13.15,30.19 12.19,30.19 12.07,30.3 12.07,31.6 11.49,32.18 11.49,32.5 11.51,32.52
LG1_ISL88738 on IN1 (solid shape): 14.02,30.52 14.02,29.81 13.88,29.67 12.33,29.67 12.14,29.86 12.14,30.54 12.37,30.77 13.76,30.77
LG1_ISL88738 on IN1 (solid shape): 20.14,30.24 20.14,29.53 20,29.39 18.45,29.39 18.26,29.58 18.26,30.27 18.49,30.5 19.88,30.5
LG2_ISL88738 on TOP (solid shape): 15.77,17.3 15.77,16.41 15.62,16.26 14.58,16.26 14.39,16.45 14.39,17.32 14.46,17.4 15.67,17.4
LG2_ISL88738 on TOP (solid shape): 10.91,32.04 10.91,31.29 10.97,31.24 10.97,30.75 11.05,30.67 11.05,30.5 11.35,30.2 11.35,30 11.22,29.87 10.89,29.87 10.54,30.23 10.54,30.64 10.71,30.82 10.71,32.04 10.72,32.05 10.9,32.05
LG2_ISL88738 on IN3 (solid shape): 16.69,18.25 16.69,17.48 15.62,16.41 15.36,16.41 15.17,16.22 14.61,16.22 14.46,16.37 14.46,17.21 14.72,17.47 15.05,17.47 15.96,18.37 16.57,18.37
LG2_ISL88738 on IN3 (solid shape): 11.2,30.45 11.37,30.23 11.64,30.19 12.42,29.41 12.42,28.74 12.39,28.71 11.79,28.71 11.72,28.78 11.72,28.92 11.12,29.53 11.12,29.54 10.56,30.1 10.56,30.65 10.69,30.77 10.89,30.77
LX1_ISL88738 on TOP (solid shape): outline of 110 points within 11.51,22.64 18.79,35.88
LX1_ISL88738 on BOTTOM (solid shape): 14.25,32.96 14.33,32.88 14.33,32.01 14.27,31.95 13.03,31.95 12.82,32.16 12.82,32.43 13.12,32.73 13.43,32.73 13.67,32.97 14.25,32.97
LX1_ISL88738 on BOTTOM (solid shape): 19.3,29.9 19.3,23 19.03,22.73 14.45,22.73 13.86,23.32 13.86,29.35 13.88,29.35 14.45,29.92 19.27,29.92
LX2_ISL88738 on TOP (solid shape): 19.03,20.98 19.03,16.79 19.6,16.22 19.6,14.34 19.39,14.12 15.1,14.12 15.03,14.19 15.03,15.96 15.1,16.03 15.67,16.03 16.18,16.53 16.18,21.04 16.49,21.36 18.65,21.36
LX2_ISL88738 on TOP (solid shape): 10.51,31.98 10.51,31.37 10.51,31.28 10.56,31.23 10.56,30.88 10.41,30.73 10.41,30.17 10.84,29.74 11.15,29.74 11.15,29.11 11.15,28.8 10.92,28.57 10.89,28.57 10.84,28.52 10.05,28.52 9.93,28.65 9.93,28.9 10.16,29.13 10.16,30.81 10.31,30.96 10.31,31.99 10.36,32.04 10.45,32.04
LX2_ISL88738 on BOTTOM (solid shape): 19.01,21.41 19.47,21.41 19.63,21.25 19.63,14.36 19.39,14.12 16.43,14.12 15.27,15.28 15.27,21.11 15.58,21.41 19.01,21.41
LX2_ISL88738 on IN3 (solid shape): 10.99,28.88 10.99,28.09 10.84,27.94 10.13,27.94 9.95,28.12 9.95,28.83 10.13,29.01 10.87,29.01
LX2_ISL88738 on IN3 (solid shape): 16.79,15.28 16.79,14.83 16.8,14.82 16.8,14.2 16.71,14.11 15.6,14.11 15.27,14.44 14.37,14.44 14.35,14.47 14.35,15.13 14.44,15.21 14.44,15.23 15.67,15.23 15.83,15.39 16.67,15.39
LX_1.8VALW on BOTTOM (solid shape): 126.44,4.72 126.56,4.72 126.61,4.67 127.35,4.67 127.68,4.34 127.68,3.53 127.63,3.48 122.22,3.48 122.09,3.61 122.09,4.85 122.2,4.95 126.21,4.95
LX_1VS_VCCIO on BOTTOM (solid shape): 149.4,60.22 150.29,60.22 150.41,60.1 150.41,59.46 150.29,59.33 148.95,59.33 146.38,56.75 143.6,56.75 142.6,57.75 142.6,58.94 142.74,59.08 143.68,59.08 144.06,59.46 144.06,59.71 144.57,60.22 147.62,60.22 148,60.6 149.02,60.6
LX_3V on TOP (solid shape): 93.2,5.68 93.2,4.03 92.88,3.71 90.98,3.71 90.85,3.83 90.85,6.12 90.98,6.25 92.63,6.25
LX_3V on BOTTOM (solid shape): 86.94,6.32 86.94,6.17 86.33,5.56 85.52,5.56 85.29,5.79 85.29,6.17 85.52,6.4 86.86,6.4
LX_3V on BOTTOM (solid shape): 94.59,5.71 97.23,5.71 97.27,5.68 97.27,2.96 97.02,2.72 93.77,2.72 91.69,4.8 90.5,4.8 89.1,6.2 89.1,6.78 89.18,6.86 93.44,6.86
LX_3V on IN1 (solid shape): 91.77,6.43 91.77,5.28 91.08,4.6 85.87,4.6 85.31,5.16 85.31,5.89 85.49,6.07 89.91,6.07 90.39,6.55 91.64,6.55
LX_5V on TOP (solid shape): 126.18,134.22 126.18,133.84 125.8,133.46 124.97,133.46 124.84,133.33 124.65,133.33 124.59,133.4 124.59,134.1 124.72,134.22 125.03,134.22 125.16,134.35 126.05,134.35
LX_5V on TOP (solid shape): 124.41,131.09 124.41,130.33 124.43,130.3 124.56,130.3 124.58,130.33 124.58,131.11 124.61,131.14 124.79,131.14 124.86,131.06 124.86,130.83 125.68,130.02 127.17,130.02 127.33,129.87 127.33,129.23 127.53,129.03 128.45,129.03 128.5,128.97 128.5,128.04 128.77,127.77 128.77,126 128.56,125.78 124.7,125.78 124.3,126.17 124.3,129.92 124.25,129.97 124.25,130 124.15,130.1 124.15,131.11 124.18,131.14 124.35,131.14
LX_5V on BOTTOM (solid shape): 126.15,134.34 126.32,134.16 126.32,133.13 126.6,132.85 127.84,132.85 127.86,132.83 129.39,132.83 129.87,132.36 129.87,126.54 129.17,125.84 124.57,125.84 124.17,126.24 124.17,128.81 124.21,128.85 124.21,128.9 124.28,128.97 124.28,129.25 124.27,129.26 124.26,129.28 124.25,129.36 124.26,129.45 124.27,129.47 124.27,129.84 125,130.57 125,134.13 125.23,134.35 126.15,134.35
LX_+1VALWP on TOP (solid shape): 173.19,5.33 173.19,4.38 173.06,4.25 170.37,4.25 170.01,4.61 170.01,5.33 170.23,5.55 172.97,5.55
LX_+1VALWP on BOTTOM (solid shape): 170.63,5.7 174.19,5.7 174.33,5.56 174.33,2.79 174.15,2.62 171.55,2.62 171,3.16 170.19,3.16 170.13,3.23 170.13,4.7 169.33,5.5 169.33,6.1 169.38,6.15 170.19,6.15
LX_+1VALWP on IN3: 166.37,5.32 171,5.32 171.2,5.12 171.2,4.94 170.99,4.72 166.52,4.72 166.2,5.04 166.2,5.16
LX_DDR on TOP (solid shape): 52.5,7.92 52.5,6.55 52.45,6.5 51.48,6.5 50.42,7.57 49.09,7.57 48.89,7.77 48.89,8.84 49.4,9.35 51.08,9.35
LX_DDR on BOTTOM (solid shape): 52.27,9.04 52.27,5.51 52.17,5.41 49.7,5.41 48.33,6.78 46.5,6.78 46.4,6.88 46.4,8.18 46.52,8.3 46.55,8.3 46.6,8.32 46.66,8.35 46.67,8.36 46.8,8.36 46.82,8.35 46.96,8.3 47.11,8.35 47.12,8.36 47.21,8.36 47.26,8.3 47.37,8.3 47.41,8.3 47.46,8.3 47.82,8.3 47.86,8.3 47.91,8.3 48,8.3 48.06,8.36 48.18,8.36 48.94,9.12 52.19,9.12
Net_3 on TOP (solid shape): 198.43,81.83 183.43,81.83 183.43,91.83 198.43,91.83
PANEL_PWRGD on BOTTOM: 152.76,97.89 153.78,97.89 154.39,97.28 154.39,95.4 154.28,95.29 152.61,95.29 152.36,95.54 152.36,97.48
PBATT+_C on TOP (solid shape): 13.32,9.75 16.09,9.75 16.36,9.48 18.13,9.48 18.44,9.18 18.44,7.26 17.45,6.27 13.56,6.27 12.85,5.56 12.85,4.98 12.62,4.75 11.88,4.75 11.78,4.85 11.78,8.23 13.31,9.76
PBATT+_C on BOTTOM (solid shape): 20.6,12.83 21.13,12.83 21.51,13.21 23.47,13.21 23.69,12.98 23.69,7.8 23.03,7.14 23.05,7.12 23.05,6.74 22.53,6.22 12.16,6.22 11.81,6.58 11.81,8.31 13.2,9.7 19.05,9.7 19.43,10.08 19.43,12.93 19.71,13.21 20.21,13.21
RING2 on TOP (solid shape): 346.47,36.63 348.37,36.63 348.56,36.44 348.56,36.18 348.44,36.06 346.59,36.06 345.58,37.07 343.99,37.07 343.93,37.14 343.93,37.2 343.99,37.26 345.83,37.26
RING2 on BOTTOM (solid shape): 348.56,36.5 348.56,36.44 348.56,36.43 348.56,35.61 348.44,35.48 346.73,35.48 346.53,35.68 346.53,36.5 346.66,36.63 348.44,36.63
RING2_R on TOP (solid shape): 353.98,35.04 355.81,35.04 355.96,34.89 355.96,33.9 355.86,33.8 355.79,33.8 355.53,33.91 355.27,33.8 355.16,33.8 354.9,33.91 354.64,33.8 352.99,33.8 352.25,34.54 352.25,35.1 352.49,35.35 353.67,35.35
RING2_R on BOTTOM (solid shape): 353.25,36.71 353.25,36.68 353.59,36.33 353.59,36.31 354.05,35.85 354.05,35.48 352.9,34.33 352.5,34.33 352.27,34.56 352.27,35.41 352.14,35.54 352.14,35.9 352,36.04 351.79,36.04 349.97,34.22 347.61,34.22 347.48,34.34 347.48,35.23 349.4,35.23 351.99,37.82 352.14,37.82
RTCRST_ON_R on TOP: 315.08,54.88 315.79,54.88 316.52,54.15 318.14,54.15 318.22,54.07 318.22,53.23 317.97,52.97 315.1,52.97 314.99,53.07 314.99,54.79
SA_SW on BOTTOM: 112.15,94.77 111.15,93.77 110.67,93.77 110.25,93.34 110.25,89.3 110.03,89.09 108.76,89.09 108.75,89.08 108.75,88.46 108.78,88.43 110.81,88.43 113.79,91.41 115.47,91.41 115.69,91.64 115.69,91.9 117.61,93.81 117.62,93.81 117.62,94.64 117.49,94.77
SLEEVE on TOP (solid shape): 345.42,37.71 345.45,37.7 345.49,37.69 345.6,37.68 345.7,37.71 346.09,37.71 346.21,37.58 348.37,37.58 348.56,37.39 348.56,37.14 348.44,37.01 346.4,37.01 345.96,37.45 343.99,37.45 343.93,37.52 343.93,37.64 343.99,37.71
SLEEVE on BOTTOM (solid shape): 348.56,38.09 348.56,37.26 348.37,37.07 346.78,37.07 346.53,37.33 346.53,38.15 346.59,38.22 348.44,38.22
SLEEVE_R on BOTTOM (solid shape): 355.77,34.76 355.77,33.13 355.64,32.99 354.85,32.99 354.67,33.18 354.67,33.76 354.59,33.83 354.3,33.83 354.07,33.6 354.07,33.23 353.92,33.09 353.55,33.09 353.55,33.09 352.97,33.09 352.79,33.27 352.79,33.85 354.16,35.22 355.3,35.22
SLEEVE_R on BOTTOM (solid shape): 351.38,38.61 351.38,37.62 351.18,37.41 350.49,37.41 350.07,37.84 350.07,38.47 349.57,38.97 349.48,38.97 349.45,38.94 349.45,38.5 349.42,38.47 347.78,38.47 347.76,38.49 347.77,38.6 347.75,38.7 347.75,39.57 347.86,39.68 348.53,39.68 349.07,40.21 349.78,40.21
SLEEVE_R on IN1 (solid shape): 356.9,32.87 356.9,32.09 356.74,31.92 356.03,31.92 355.2,32.76 354.79,32.76 354.5,33.04 354.5,33.65 354.63,33.77 356,33.77
SLEEVE_R on IN3 (solid shape): 351.24,38.74 351.24,35.38 352.4,34.22 353.71,34.22 354.06,33.86 354.06,33.3 353.83,33.07 352.19,33.07 352.11,33.15 351.73,33.15 349.99,34.88 349.99,38.97 350.21,39.18 350.79,39.18
SNUB_1.8VALW on BOTTOM (solid shape): 127.99,5.59 127.99,5.08 128.06,5 128.7,5 128.82,4.88 128.82,4.27 128.8,4.24 127.96,4.24 127.4,4.8 126.67,4.8 126.59,4.88 126.59,5.66 126.72,5.79 127.78,5.79
SNUB_1VS_VCCIO on BOTTOM (solid shape): 143.65,60.39 143.65,59.5 141.61,59.5 141.56,59.55 141.56,60.34 141.74,60.52 143.52,60.52
SNUB_+1VALWP on TOP (solid shape): 173.19,3.16 173.19,1.84 172.97,1.63 170.81,1.63 170.44,1.99 170.44,3.03 170.67,3.26 173.08,3.26
SNUB_CHG1 on TOP (solid shape): 13.55,24.51 13.55,22.82 13.49,22.75 12.56,22.75 12.42,22.89 12.42,23.51 12.07,23.86 11.28,23.86 11.11,24.04 11.11,24.53 11.27,24.69 13.37,24.69
SNUB_CHG2 on TOP (solid shape): 13.5,16.64 13.5,14.2 13.28,13.98 12.38,13.98 12.15,14.21 12.15,16.7 12.28,16.83 13.31,16.83
TBTA_CC1 on TOP: 10.93,114.14 14.22,114.14 14.88,113.47 14.88,112.56 14.75,112.43 14.49,112.43 13.16,113.75 10.42,113.75 9.68,113.02 9.16,113.02 9.05,113.13 9.05,113.56 9.57,114.07 10.87,114.07
UG1_ISL88738 on TOP (solid shape): 17.73,31.86 17.73,30.96 17.51,30.75 16.33,30.75 16.2,30.87 16.2,31.85 16.38,32.03 17.56,32.03
UG1_ISL88738 on TOP (solid shape): 13.51,33.24 13.51,33.04 13.34,32.88 12.56,32.88 12.37,33.07 11.58,33.07 11.51,33.13 11.51,33.28 11.56,33.32 12.87,33.32 12.88,33.32 13.08,33.32 13.14,33.38 13.36,33.38
UG1_ISL88738 on IN1 (solid shape): 14.31,33.25 14.31,32.82 14.13,32.64 12.44,32.64 12.37,32.71 12.37,33.26 12.54,33.44 14.12,33.44
UG1_ISL88738 on IN1 (solid shape): 17.79,31.76 17.79,31.08 17.37,30.66 16.16,30.66 15.91,30.91 15.91,31.72 16.24,32.05 17.5,32.05
UG2_ISL88738 on TOP (solid shape): 22.35,17.59 22.35,16.85 22.12,16.62 20.86,16.62 20.86,16.62 20.75,16.73 20.75,17.61 20.82,17.69 22.25,17.69
UG2_ISL88738 on TOP (solid shape): 10.11,32.03 10.11,30.96 10.03,30.89 10.03,30.02 9.93,29.92 9.7,29.92 9.57,30.05 9.57,30.81 9.91,31.14 9.91,32 9.97,32.06 10.07,32.06
UG2_ISL88738 on IN3 (solid shape): 22.36,17.77 22.36,16.89 22.17,16.7 21.72,16.7 21.18,17.24 20.34,17.24 20.06,17.52 20.06,17.91 20.17,18.02 22.12,18.02
UG2_ISL88738 on IN3 (solid shape): 10.03,30.84 10.03,29.46 9.29,28.73 8.86,28.73 8.73,28.85 8.73,29.46 9.04,29.77 9.04,30.28 9.7,30.94 9.93,30.94
N16775433 on TOP (solid shape): 54.78,9.17 54.78,7.9 54.5,7.62 52.78,7.62 52.7,7.7 52.7,9.35 52.75,9.4 54.56,9.4
N16775513 on TOP (solid shape): 51.13,6.2 52.27,6.2 52.47,5.99 52.47,5.16 52.42,5.1 50.42,5.1 50.27,5.25 50.27,6.32 50.32,6.37 50.95,6.37
N16775517 on TOP (solid shape): 49.58,6.35 49.58,5.41 49.48,5.31 48.18,5.31 48.1,5.38 48.1,6.27 48.21,6.37 49.55,6.37
N16775517 on BOTTOM (solid shape): 48.88,6.01 48.88,5.46 48.77,5.36 48.21,5.36 47.7,5.87 47.7,6.35 47.75,6.4 48.48,6.4
N18739956 on TOP (solid shape): 347.04,38.58 347.04,37.71 346.28,37.71 346.15,37.84 343.99,37.84 343.93,37.9 343.93,38.03 343.99,38.09 345.77,38.09 346.34,38.66 346.96,38.66
N20816750 on BOTTOM: 43.76,64.52 42.82,64.52 42.69,64.64 42.01,64.64 41.91,64.74 41.91,65.53 42.01,65.63 42.57,65.63 42.74,65.46 42.74,65.05 42.9,64.9 43.79,64.9 43.89,64.79 43.89,64.64
N20816752 on BOTTOM: 42.54,66.88 41.96,66.88 41.93,66.85 41.93,65.91 41.96,65.89 42.62,65.89 42.97,65.53 43.79,65.53 43.84,65.58 43.84,65.81 43.79,65.86 43.15,65.86 42.69,66.32 42.69,66.73
N20816771 on BOTTOM: 41.2,66.86 40.59,66.86 40.52,66.78 40.52,64.76 40.61,64.68 41.19,64.68 41.24,64.72 41.24,66.82
N20816800 on BOTTOM: 50.47,61.24 49.48,61.24 49.37,61.14 49.37,58.22 49.53,58.06 50.47,58.06 50.62,58.22 50.62,61.09
N20816821 on BOTTOM (solid shape): 104.81,93.54 104.81,93.19 105.37,92.63 105.95,92.63 106.08,92.5 106.08,92.42 105.97,92.31 105.13,92.31 104.83,92.62 104.09,92.62 104.03,92.68 104.03,93.55 104.07,93.59 104.76,93.59
N20816822 on BOTTOM (solid shape): 104.86,92.3 104.86,92.09 105.34,91.61 106.03,91.61 106.1,91.54 106.1,91.33 106.03,91.26 105.26,91.26 105.15,91.36 104.06,91.36 103.97,91.45 103.97,92.35 104,92.37 104.79,92.37
N20816832 on BOTTOM (solid shape): 106.05,90.55 106.05,90.39 105.99,90.32 105.1,90.32 104.59,89.81 104.59,88.09 104.56,88.05 103.71,88.05 103.67,88.1 103.67,89.94 103.7,89.98 104.03,90.31 104.79,90.31 105.03,90.55 105.24,90.55 105.34,90.65 105.95,90.65
N20816859 on BOTTOM: 103.42,93.62 102.66,93.62 102.54,93.5 102.54,91.57 102.69,91.41 103.37,91.41 103.45,91.49 103.45,93.6
N20816888 on BOTTOM (solid shape): 117.42,96.32 117.42,95.43 117.34,95.35 115.21,95.35 115.03,95.53 115.03,97.46 115.11,97.54 116.2,97.54
N24493415 on BOTTOM: 146.4,93.6 147.48,93.6 147.79,93.29 148.48,93.29 148.52,93.26 148.52,92.04 148.36,91.87 146.07,91.87 145.96,91.99 145.96,92.39 146.33,92.76 146.33,93.52
N26116940 on TOP (solid shape): 67.79,120.12 67.79,119.58 67.7,119.49 66.77,119.49 66.65,119.62 66.65,120.37 66.77,120.5 67.41,120.5
N27933518 on TOP (solid shape): 95.19,100.56 95.19,99.78 95.16,99.75 93.97,99.75 93.9,99.82 93.9,100.61 93.98,100.69 95.06,100.69
N27933520 on TOP (solid shape): 95.12,99.39 95.12,98.68 95.1,98.66 94.61,98.66 94.5,98.55 93.9,98.55 93.87,98.58 93.87,99.4 93.9,99.44 95.07,99.44
N27933520 on BOTTOM: 94.86,99.36 95.02,99.36 95.44,98.94 96.01,98.94 96.07,98.88 96.07,98.68 96.01,98.62 94.84,98.62 94.66,98.8 94.66,99.16
N27933540 on TOP (solid shape): 95.09,96.6 95.09,95.82 95.07,95.81 93.92,95.81 93.84,95.89 93.84,96.53 93.93,96.62 95.07,96.62
N27933540 on BOTTOM (solid shape): 96.06,97.9 96.06,97.7 95.96,97.6 95.09,97.6 95.03,97.55 94.85,97.55 94.52,97.21 94.52,96.32 94.24,96.04 93.87,96.04 93.48,96.43 93.48,97.66 93.66,97.84 94.97,97.84 95.06,97.93 96.02,97.93
N27933602 on TOP (solid shape): 96.03,100.63 96.03,98.63 95.96,98.56 95.37,98.56 95.3,98.63 95.3,99.68 95.36,99.74 95.36,100.62 95.4,100.66 95.99,100.66
N27933660 on TOP: 98.79,95.4 97.83,95.4 97.79,95.36 97.79,92.56 97.94,92.41 98.74,92.41 98.85,92.52 98.85,95.34
N30393649 on TOP (solid shape): 171.59,9.42 171.59,8.97 171.51,8.89 170.05,8.89 169.82,8.66 169.57,8.66 169.33,8.9 169.33,9.07 169.83,9.58 171.43,9.58
N30393649 on BOTTOM: 168.58,10.91 170.39,10.91 170.51,10.79 170.51,10.26 170.43,10.18 170.16,10.18 169.92,9.94 169.92,9.38 169.9,9.36 169.39,9.36 169.39,9.94 169.07,10.26 168.53,10.26 168.51,10.27 168.51,10.85
N30393661 on TOP (solid shape): 171.59,11.16 171.59,9.83 171.51,9.75 170.2,9.75 170.15,9.8 170.15,10.71 170.73,11.29 171.46,11.29
N36423841 on BOTTOM (solid shape): 91.69,4.11 91.69,3.5 91.59,3.4 89.61,3.4 89.58,3.43 89.58,4.65 89.61,4.67 91.13,4.67
N36423890 on TOP (solid shape): 128.6,131.24 128.6,129.49 128.55,129.44 127.61,129.44 127.58,129.46 127.58,130.14 127.86,130.41 127.86,131.28 127.92,131.34 128.49,131.34
N37229012 on TOP (solid shape): 123.52,131.09 123.52,130 123.31,129.79 122.75,129.79 122.6,129.64 122.6,129.13 122.2,128.73 121.54,128.73 121.51,128.75 121.51,129.97 121.61,130.07 121.76,130.07 122.83,131.14 123.47,131.14
N37410469 on TOP (solid shape): 91.34,10.69 91.34,9.51 91.33,9.51 91.33,8.76 91.11,8.53 90.09,8.53 89.96,8.66 89.96,10.34 90.44,10.81 91.22,10.81
N37410469 on BOTTOM (solid shape): 91.54,10.26 91.54,8.58 91.53,8.58 90.53,7.59 90.06,7.59 89.96,7.49 89.15,7.49 89.1,7.54 89.1,8.2 89.66,8.76 89.66,10.3 89.69,10.37 89.7,10.44 91.36,10.44
N42077965 on BOTTOM (solid shape): 71.96,102 71.96,101.42 71.37,100.83 71.37,100.27 71.27,100.17 71.16,100.17 71.04,100.29 71.04,102.01 71.06,102.03 71.93,102.03
N42077969 on BOTTOM (solid shape): 70.76,101.98 70.76,101.19 70.37,100.8 70.37,100.27 70.27,100.16 70.17,100.16 70.07,100.27 70.07,101.15 69.84,101.38 69.84,102.01 69.85,102.02 70.72,102.02
N42077993 on BOTTOM: 68.58,101.41 67.36,101.41 67.17,101.6 67.17,102.8 67.25,102.88 67.25,102.88 68.5,102.88 68.67,102.71 68.67,101.95 68.67,101.95 68.67,101.5
N42078041 on TOP: 80.02,102.77 80.86,102.77 80.93,102.69 80.93,101.27 80.84,101.18 80.18,101.18 80.06,101.31 80.06,101.68 79.93,101.8 79.93,102.68
N42078055 on TOP: 78.88,102.76 79.66,102.76 79.78,102.64 79.78,101.71 79.92,101.57 79.92,101.23 79.73,101.04 79.17,101.04 78.98,101.23 78.98,101.7 78.72,101.96 78.72,102.6
N42078421 on BOTTOM (solid shape): 72.03,103.41 72.03,102.78 71.98,102.72 69.89,102.72 69.84,102.78 69.84,103.41 69.87,103.44 72.01,103.44
N42078543 on TOP: 74.15,92.73 73.28,92.73 73.18,92.64 73.18,90.77 73.22,90.73 75.41,90.73 75.54,90.86 75.54,91.34 75.42,91.46 74.67,91.46 74.29,91.84 74.29,92.6
N42078657 on TOP (solid shape): 80.84,104.16 80.84,103.54 80.75,103.46 78.74,103.46 78.67,103.53 78.67,104.11 78.79,104.23 80.77,104.23
N42078671 on TOP: 76.82,103.21 77.85,103.21 78.42,102.64 78.42,102.11 78.88,101.65 78.88,101.26 78.75,101.13 78.39,101.13 78.29,101.23 78.29,101.62 78.16,101.75 77.72,101.75 77.61,101.64 76.74,101.64 76.69,101.69 76.69,103.09
N42078715 on TOP: 82.51,94.57 80.21,94.57 79.81,94.16 79.81,92.92 80.06,92.66 82.51,92.66 82.62,92.78 82.62,94.46
N42079748 on TOP: 85.3,99.24 86.33,99.24 86.42,99.15 86.42,98.33 86.33,98.25 85.86,98.25 85.49,98.62 85.18,98.62 85.11,98.69 85.11,99.04
N42079752 on TOP: 85.31,100.45 86.29,100.45 86.35,100.4 86.35,99.5 86.27,99.42 85.18,99.42 85.08,99.51 85.08,100.23
N42079902 on TOP: 84.29,100.42 84.88,100.42 84.98,100.33 84.98,98.27 84.93,98.23 84.43,98.23 84.32,98.33 84.32,99.17 84.29,99.2 84.28,99.2 84.28,100.42
N42079910 on BOTTOM (solid shape): 86.42,97.7 86.42,97.61 86.33,97.51 85.48,97.51 84.94,96.97 84.94,96.37 85.29,96.03 85.29,95.61 85.2,95.52 84.13,95.52 83.96,95.69 83.96,97.41 83.96,97.59 84.01,97.65 85.32,97.65 85.5,97.82 86.31,97.82
N42079960 on TOP: 90.76,95.66 89.48,95.66 89.34,95.52 89.34,92.72 89.39,92.67 90.56,92.67 90.8,92.91 90.8,95.61
N132000604 on TOP (solid shape): 11.17,28.35 11.17,27.71 11.15,27.69 8.99,27.69 8.96,27.71 8.96,28.35 8.99,28.37 11.15,28.37

Small or netless copper shapes (teardrops, artwork), in the pictures only: 332 on TOP, 39 on BOTTOM, 9 on IN1, 4 on IN2, 39 on IN3

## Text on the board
Ref Des/Silkscreen Bottom: DIMM A | DDR4 | DIMM B | A | H34 | H35 | H16 | H7 | H8 | GXXF6 | REV:X02 | PWB PN: | ALL RIGHT RESERVED | COPYRIGHT 2018
User.Comments: CR_PCH_1 | PARTITION_2 | PARTITION_3 | PARTITION_2-23 | LA-F711P | DDP80 | 2019-01-12 | Sunny | 2018-01-12
COMPVAL_TYPE_BOTTOM: L7 | L8
User.43: FIGURE | SIZE | 8.0 | 20.0 | 28.0 | 35.0 | 39.0 | 94.0 | 102.0 | 126.0 | 130.0 | 150.0 | 181.0 | 201.0 | 205.0 | 31.0 | 40.0 | 43.0 | 63.0 | 71.0 | 49.0x28.0 | 55.0x24.0 | 59.0x28.0 | 67.0x31.0 | 71.0x31.0 | 75.0x24.0 | 94.0x28.0 | 100.0x31.0 | 102.0x31.0 | 94.0x71.0 | 197.0x157.0 | DRILL CHART: TOP to BOTTOM | ALL UNITS ARE IN MILS | TOLERANCE | +3.0/-3.0 | +2.0/-2.0 | PLATED | NON-PLATED | QTY | 538 | 7172 | 19 | 42 | 10 | 5 | 4 | 2 | 1 | 3 | 6 | 7
User.44: Width/space | 4.4 / 3.5 | 4 / 3.5 | 3.5 / 4.7 | 80 ohm
